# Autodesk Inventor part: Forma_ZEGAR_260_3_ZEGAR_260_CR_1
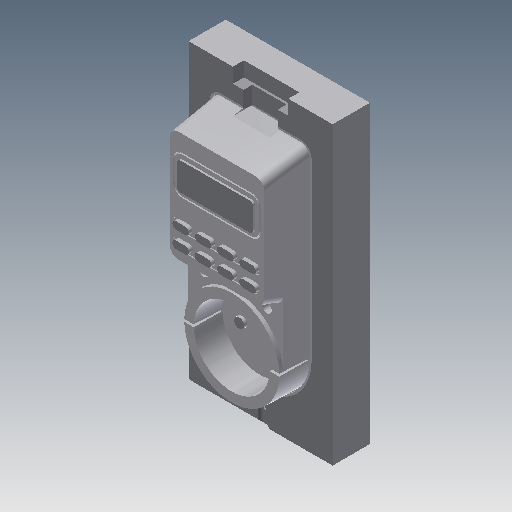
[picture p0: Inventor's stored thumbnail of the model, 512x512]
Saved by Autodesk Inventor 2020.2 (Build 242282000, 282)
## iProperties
Created: 2015-01
Part Number: Forma_ZEGAR_260_3_ZEGAR_260_CR_1
Material: Ogólny
Document SubType Name: Modeling
Designer: F.Stasiak
Density: 1 g/cm^3
Appearance: Domyślna
Catalog Web Link: www.expertbooks.pl
Manager: www.cadconsulting.pl
Company: Fabian Stasiak CAD Consulting
Author: F.Stasiak
Subject: Zbiór ćwiczeń. Autodesk Inventor 2020. Kurs Professional
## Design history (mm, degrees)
node "Forma_ZEGAR_260_3_ZEGAR_260_CR_Base"
feature "Rzeźbienie3"
feature "Bryła1::Forma_ZEGAR_260_3_ZEGAR_260_CR_Base"
tag "Bryła wyprowadzona1"
node "Bryła1"
feature "Forma_ZEGAR_260_3_ZEGAR_260_CR_Base_Bodies"
feature "Powierzchnia3"
body "Srf3"
